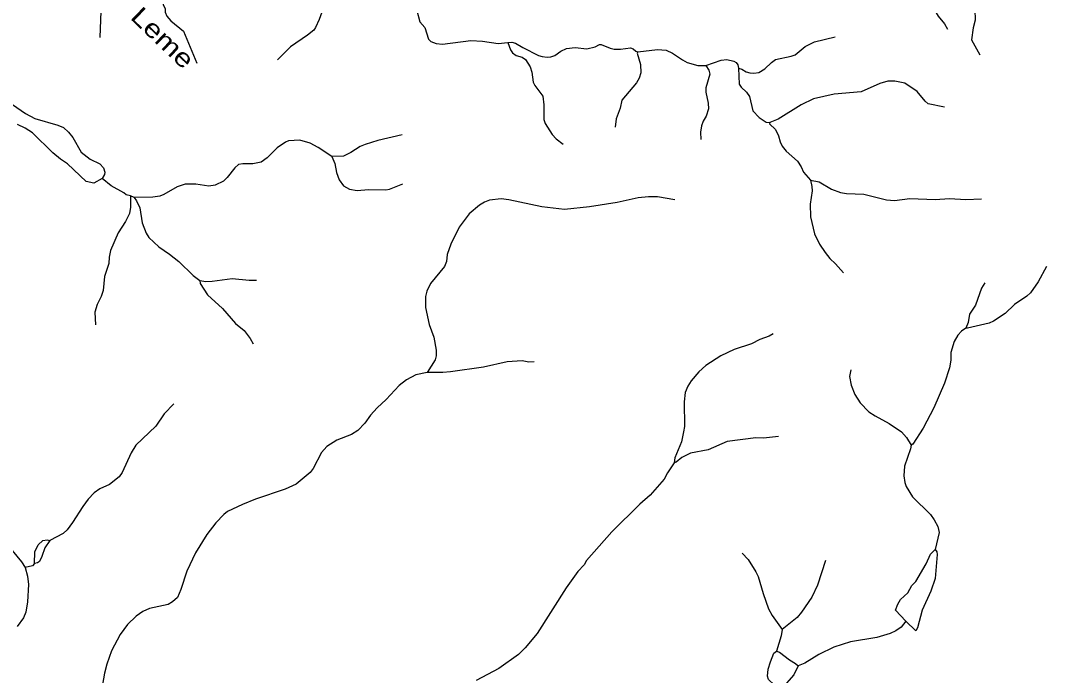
# Model space of a CAD drawing. Extents: x 320.3 to 346.3, y 7455.4 to 7483.3.
# Drawn here: x 336.33 to 340.889, y 7468.339 to 7471.246 of the extents above; entities that cross this region are included whole.
import ezdxf
from ezdxf.enums import TextEntityAlignment as Align

# ---------------------------------------------------------------- set-up
doc = ezdxf.new("R2010")
doc.units = 0
doc.header["$LTSCALE"] = 0.032
doc.layers.add('2', color=7, linetype='Continuous', lineweight=25)
doc.layers.add('7', color=7, linetype='Continuous', lineweight=25)
doc.layers.add('61', color=7, linetype='Continuous')

msp = doc.modelspace()

# ---------------------------------------------------------------- linework, layer by layer
at = {"layer": '2'}
for points in [[(336.2936, 7470.8732), (336.3515, 7470.8329), (336.3936, 7470.8111), (336.495, 7470.7824), (336.5211, 7470.7708), (336.5435, 7470.7511), (336.5628, 7470.7274), (336.5991, 7470.6626), (336.6389, 7470.6306), (336.682, 7470.6101), (336.6983, 7470.5923), (336.7044, 7470.5734), (336.7024, 7470.5629), (336.6931, 7470.5457), (336.6551, 7470.525), (336.6209, 7470.5323), (336.5385, 7470.6101), (336.5073, 7470.6312), (336.4734, 7470.6595), (336.3826, 7470.7483), (336.3499, 7470.7691), (336.3167, 7470.7855)], [(336.2435, 7468.9524), (336.334, 7468.8432), (336.3502, 7468.8174), (336.3614, 7468.7803), (336.3657, 7468.7427), (336.3613, 7468.6653), (336.353, 7468.6196), (336.3435, 7468.5944), (336.3141, 7468.5555)]]:
    msp.add_lwpolyline(points, dxfattribs=at)
for points in [[(336.3924, 7468.8355), (336.3939, 7468.8883), (336.408, 7468.9181), (336.4286, 7468.9375), (336.448, 7468.9407), (336.4593, 7468.9373), (336.4376, 7468.9053), (336.4245, 7468.8662), (336.4139, 7468.845), (336.405, 7468.8385)], [(340.2172, 7468.6285), (340.2278, 7468.655), (340.2404, 7468.6762), (340.2723, 7468.7057), (340.2904, 7468.7381), (340.3077, 7468.7554), (340.3544, 7468.8343), (340.3739, 7468.877), (340.3939, 7468.8982), (340.4012, 7468.8874), (340.4028, 7468.8754), (340.394, 7468.7697), (340.3751, 7468.7135), (340.3368, 7468.6293), (340.3156, 7468.5495), (340.3078, 7468.5362), (340.2642, 7468.5802)], [(339.6484, 7468.3352), (339.6519, 7468.3668), (339.6621, 7468.3988), (339.6775, 7468.4374), (339.689, 7468.4466), (339.7019, 7468.4428), (339.7462, 7468.408), (339.7741, 7468.3923), (339.785, 7468.381), (339.7659, 7468.3418), (339.7113, 7468.28), (339.7034, 7468.2741), (339.6791, 7468.2965), (339.653, 7468.3207)]]:
    msp.add_lwpolyline(points, close=True, dxfattribs=at)
at = {"layer": '7'}
msp.add_line((336.8346, 7470.4601), (336.818, 7470.4679), dxfattribs=at)
for points in [[(337.8245, 7471.6577), (337.8019, 7471.6177), (337.7682, 7471.5712), (337.7578, 7471.5468), (337.7362, 7471.4713), (337.7184, 7471.4348), (337.6965, 7471.4031), (337.6821, 7471.3734), (337.6709, 7471.3345), (337.6679, 7471.2832), (337.6572, 7471.2506), (337.6412, 7471.2156), (337.6326, 7471.2039), (337.6054, 7471.1817), (337.5299, 7471.1296), (337.4719, 7471.0718)], [(340.5465, 7471.6575), (340.5307, 7471.6427), (340.5107, 7471.6328), (340.4993, 7471.6329), (340.4717, 7471.6431), (340.463, 7471.6431), (340.4505, 7471.6351), (340.437, 7471.617), (340.3878, 7471.5971), (340.374, 7471.5652), (340.3702, 7471.528), (340.3492, 7471.4691), (340.3399, 7471.4106), (340.341, 7471.3886), (340.3486, 7471.3651), (340.4079, 7471.2651), (340.4358, 7471.2317), (340.4495, 7471.2085)], [(336.6313, 7471.5267), (336.6561, 7471.5244), (336.6661, 7471.52), (336.6994, 7471.4935), (336.7308, 7471.4557), (336.7439, 7471.4481), (336.7738, 7471.4366), (336.8591, 7471.4186), (336.8819, 7471.4086), (336.8942, 7471.3985), (336.9149, 7471.3903), (336.9351, 7471.3743), (336.9577, 7471.3423), (336.9644, 7471.3133), (336.9719, 7471.3004), (336.9723, 7471.2834), (336.9801, 7471.2654), (336.9981, 7471.2449), (337.0541, 7471.1998), (337.1139, 7471.0573)], [(336.6313, 7471.5267), (336.6701, 7471.4709), (336.6945, 7471.4072), (336.6984, 7471.3518), (336.6872, 7471.288), (336.6827, 7471.1715)], [(340.6429, 7471.4321), (340.6321, 7471.3986), (340.5829, 7471.3306), (340.5708, 7471.2959), (340.5716, 7471.2481), (340.5624, 7471.2141), (340.556, 7471.1605), (340.5919, 7471.0943)], [(338.0912, 7471.2904), (338.1045, 7471.24), (338.1259, 7471.2152), (338.1421, 7471.164), (338.1528, 7471.1538), (338.1771, 7471.1445), (338.2053, 7471.1416), (338.3308, 7471.1575), (338.3822, 7471.1548), (338.4515, 7471.1441), (338.4949, 7471.1485)], [(339.5196, 7471.0354), (339.5345, 7471.0305), (339.5541, 7471.0189), (339.5705, 7471.0144), (339.5886, 7471.013), (339.6112, 7471.0162), (339.6368, 7471.0317), (339.6668, 7471.0606), (339.6849, 7471.0734), (339.7548, 7471.0874), (339.7719, 7471.0936), (339.8164, 7471.1314), (339.8573, 7471.1522), (339.9498, 7471.174)], [(338.4949, 7471.1485), (338.5132, 7471.1502), (338.5288, 7471.1458), (338.5621, 7471.1261), (338.6307, 7471.0914), (338.6482, 7471.0866), (338.6703, 7471.0841), (338.6864, 7471.0852), (338.7047, 7471.0911), (338.7311, 7471.11), (338.7556, 7471.1218), (338.7942, 7471.127), (338.8467, 7471.1212), (338.8836, 7471.1302), (338.9023, 7471.1406), (338.9102, 7471.1401), (338.9497, 7471.123), (338.968, 7471.1188), (338.9956, 7471.1199), (339.0398, 7471.1258), (339.0525, 7471.1214), (339.0633, 7471.1105), (339.0732, 7471.1079)], [(338.4949, 7471.1485), (338.5069, 7471.1158), (338.5166, 7471.1024), (338.5321, 7471.0918), (338.5593, 7471.0839), (338.5743, 7471.0736), (338.5938, 7471.0409), (338.6012, 7471.0178), (338.6081, 7470.9723), (338.6156, 7470.9575), (338.6505, 7470.91), (338.6553, 7470.8724), (338.6554, 7470.8069), (338.6607, 7470.7899), (338.6916, 7470.7402), (338.7094, 7470.7211), (338.7414, 7470.6977)], [(339.0732, 7471.1079), (339.0705, 7471.1008), (339.0847, 7471.0516), (339.0866, 7471.0137), (339.0784, 7470.99), (339.0672, 7470.9704), (339.0019, 7470.8931), (338.9939, 7470.8574), (338.9758, 7470.8099), (338.9723, 7470.7733)], [(339.0732, 7471.1079), (339.1596, 7471.1175), (339.1993, 7471.115), (339.227, 7471.1011), (339.2709, 7471.0713), (339.2924, 7471.0603), (339.3391, 7471.0469), (339.3757, 7471.0467)], [(339.3757, 7471.0467), (339.4432, 7471.0701), (339.4684, 7471.0727), (339.4992, 7471.0655), (339.5098, 7471.0597), (339.5167, 7471.0496), (339.5196, 7471.0354)], [(339.3757, 7471.0467), (339.388, 7471.0262), (339.3922, 7471.0088), (339.3746, 7470.947), (339.3753, 7470.9276), (339.3854, 7470.8798), (339.3863, 7470.8547), (339.3767, 7470.8219), (339.3634, 7470.7993), (339.3561, 7470.7789), (339.3507, 7470.7507), (339.3521, 7470.7178)], [(339.5196, 7471.0354), (339.5225, 7470.9642), (339.5317, 7470.95), (339.5557, 7470.9287), (339.5691, 7470.9098), (339.5842, 7470.8452), (339.612, 7470.8158), (339.6437, 7470.7957), (339.6587, 7470.7937)], [(340.4358, 7470.861), (340.3624, 7470.877), (340.3491, 7470.8886), (340.3141, 7470.931), (340.2595, 7470.9677), (340.2144, 7470.9767), (340.1844, 7470.977), (340.1478, 7470.9672), (340.0648, 7470.9305), (339.945, 7470.9189), (339.8528, 7470.8986), (339.7986, 7470.8721), (339.6966, 7470.8082), (339.6587, 7470.7937)], [(339.6587, 7470.7937), (339.6585, 7470.7883), (339.6842, 7470.7622), (339.6974, 7470.7348), (339.7046, 7470.7072), (339.7139, 7470.6881), (339.7324, 7470.6659), (339.7823, 7470.6213), (339.799, 7470.5975), (339.8085, 7470.5727), (339.8398, 7470.5382)], [(337.7138, 7470.6424), (337.6522, 7470.6832), (337.6164, 7470.7018), (337.5709, 7470.715), (337.5201, 7470.7118), (337.5077, 7470.707), (337.4707, 7470.6813), (337.4258, 7470.6367), (337.3991, 7470.6181), (337.3627, 7470.6099), (337.3172, 7470.6107), (337.2986, 7470.6075), (337.282, 7470.5924), (337.2473, 7470.5488), (337.2311, 7470.5331), (337.1947, 7470.5151), (337.1664, 7470.5112), (337.108, 7470.5192), (337.0617, 7470.52), (337.0262, 7470.5074), (336.9672, 7470.4736), (336.9481, 7470.4673), (336.9173, 7470.4617), (336.8346, 7470.4601)], [(338.0254, 7470.7395), (337.9168, 7470.7144), (337.8605, 7470.6967), (337.8387, 7470.6873), (337.7978, 7470.6604), (337.7653, 7470.6437), (337.7138, 7470.6424)], [(337.7138, 7470.6424), (337.7269, 7470.6112), (337.7344, 7470.5712), (337.7452, 7470.539), (337.7644, 7470.5124), (337.7912, 7470.4981), (337.8257, 7470.4917), (337.8754, 7470.4964), (337.9525, 7470.4942), (337.9696, 7470.4975), (338.0286, 7470.5207)], [(336.818, 7470.4679), (336.7995, 7470.4718), (336.7884, 7470.4821), (336.7328, 7470.5129), (336.6931, 7470.5457)], [(339.8398, 7470.5382), (339.8463, 7470.5099), (339.8469, 7470.49), (339.838, 7470.4308), (339.8396, 7470.3754), (339.8578, 7470.3001), (339.8798, 7470.2536), (339.905, 7470.2167), (339.9259, 7470.19), (339.9514, 7470.1664), (339.9869, 7470.1257)], [(339.8398, 7470.5382), (339.8793, 7470.5308), (339.934, 7470.4979), (339.9737, 7470.4836), (340.0005, 7470.4789), (340.0766, 7470.4755), (340.1784, 7470.4503), (340.214, 7470.4481), (340.2822, 7470.456), (340.3942, 7470.4512), (340.4574, 7470.4558), (340.5303, 7470.4512), (340.5999, 7470.4547)], [(336.818, 7470.4679), (336.8191, 7470.4179), (336.8141, 7470.3903), (336.7968, 7470.3545), (336.7638, 7470.3032), (336.7296, 7470.2249), (336.7235, 7470.1959), (336.7217, 7470.1672), (336.7033, 7470.1105), (336.6966, 7470.0484), (336.6877, 7470.0212), (336.6708, 7469.9861), (336.6604, 7469.9521), (336.6634, 7469.8956)], [(336.8346, 7470.4601), (336.8451, 7470.4459), (336.8599, 7470.415), (336.8701, 7470.3488), (336.8884, 7470.3021), (336.9006, 7470.2837), (336.9445, 7470.2424), (336.9922, 7470.2094), (337.0325, 7470.1759), (337.097, 7470.1138), (337.1271, 7470.0916)], [(339.237, 7470.4499), (339.1595, 7470.4632), (339.1203, 7470.4639), (339.0737, 7470.4588), (338.9813, 7470.4379), (338.8581, 7470.4188), (338.7468, 7470.4081), (338.6456, 7470.4197), (338.5003, 7470.4509), (338.465, 7470.4549), (338.4142, 7470.4483), (338.3914, 7470.4399), (338.3686, 7470.427), (338.3238, 7470.3887), (338.2794, 7470.3293), (338.2413, 7470.2537), (338.2263, 7470.2073), (338.2219, 7470.177), (338.2143, 7470.1537), (338.1519, 7470.0784), (338.1351, 7470.0453), (338.1292, 7470.0206), (338.1297, 7469.972), (338.1457, 7469.8965), (338.1661, 7469.84), (338.1774, 7469.7828), (338.1772, 7469.7578), (338.1727, 7469.7397), (338.1367, 7469.6844)], [(340.8887, 7470.1546), (340.8515, 7470.0865), (340.8178, 7470.0378), (340.8016, 7470.023), (340.7464, 7469.9863), (340.7045, 7469.9454), (340.6532, 7469.912), (340.6334, 7469.903), (340.5373, 7469.8803), (340.53, 7469.8809)], [(337.1271, 7470.0916), (337.1538, 7470.0881), (337.1808, 7470.0893), (337.2709, 7470.1014), (337.3452, 7470.0931), (337.3786, 7470.0943)], [(337.1271, 7470.0916), (337.1279, 7470.0788), (337.1599, 7470.0289), (337.2279, 7469.9673), (337.2846, 7469.9017), (337.3231, 7469.8705), (337.3503, 7469.8342), (337.3641, 7469.8103)], [(340.6153, 7470.082), (340.6003, 7470.0585), (340.5729, 7469.9832), (340.5462, 7469.9431), (340.5407, 7469.9056), (340.53, 7469.8809)], [(340.53, 7469.8809), (340.511, 7469.8677), (340.4945, 7469.8495), (340.4788, 7469.8209), (340.4634, 7469.7722), (340.4631, 7469.7378), (340.458, 7469.7052), (340.4362, 7469.6371), (340.3886, 7469.5274), (340.3403, 7469.4364), (340.2948, 7469.3663), (340.2875, 7469.3614)], [(339.6747, 7469.8561), (339.6566, 7469.8453), (339.6151, 7469.8305), (339.5773, 7469.8113), (339.5011, 7469.7858), (339.4416, 7469.7578), (339.3749, 7469.7141), (339.3434, 7469.6863), (339.3093, 7469.6472), (339.2947, 7469.6233), (339.2834, 7469.5955), (339.2781, 7469.5542), (339.2796, 7469.4444), (339.2762, 7469.4201), (339.2666, 7469.3763), (339.2372, 7469.3044), (339.2348, 7469.2823)], [(338.6127, 7469.7306), (338.5878, 7469.7301), (338.5587, 7469.7349), (338.4922, 7469.7317), (338.3871, 7469.7081), (338.2404, 7469.6871), (338.207, 7469.6832), (338.1367, 7469.6844)], [(340.019, 7469.696), (340.0135, 7469.6659), (340.0214, 7469.627), (340.0378, 7469.5868), (340.0615, 7469.549), (340.0996, 7469.5096), (340.1273, 7469.4912), (340.1897, 7469.4576), (340.2441, 7469.4199), (340.2674, 7469.3959), (340.2875, 7469.3614)], [(338.1367, 7469.6844), (338.0857, 7469.6735), (338.0452, 7469.6517), (338.0129, 7469.6264), (337.9546, 7469.5633), (337.9139, 7469.5274), (337.8852, 7469.4943), (337.8597, 7469.4583), (337.8286, 7469.4268), (337.8009, 7469.4082), (337.7353, 7469.3838), (337.6908, 7469.3547), (337.6671, 7469.329), (337.6295, 7469.2577), (337.6161, 7469.2393), (337.5541, 7469.1881), (337.5064, 7469.1655), (337.3745, 7469.1215), (337.3168, 7469.098), (337.249, 7469.0663), (337.2326, 7469.0528), (337.1978, 7469.0161), (337.1577, 7468.9645), (337.1073, 7468.8838), (337.0682, 7468.8022), (337.0427, 7468.7197), (337.0267, 7468.6852), (337.0052, 7468.6656), (336.9851, 7468.6544), (336.9035, 7468.6354), (336.8727, 7468.622), (336.8439, 7468.6026), (336.8052, 7468.5653), (336.7729, 7468.5206), (336.7344, 7468.4484), (336.7134, 7468.3887), (336.7025, 7468.3484), (336.6946, 7468.2985)], [(337.0117, 7469.5448), (336.9681, 7469.4997), (336.9314, 7469.4454), (336.8427, 7469.3614), (336.8213, 7469.3273), (336.782, 7469.2397), (336.7679, 7469.2207), (336.725, 7469.187), (336.6827, 7469.167), (336.6566, 7469.149), (336.6305, 7469.1216), (336.6059, 7469.0895), (336.5614, 7469.0174), (336.5376, 7468.9855), (336.5197, 7468.9684), (336.4593, 7468.9373)], [(339.6972, 7469.3992), (339.6306, 7469.3919), (339.5973, 7469.3939), (339.4702, 7469.377), (339.385, 7469.341), (339.307, 7469.3257), (339.2685, 7469.3063), (339.2432, 7469.2852), (339.2348, 7469.2823)], [(340.2875, 7469.3614), (340.285, 7469.3449), (340.2577, 7469.2672), (340.2549, 7469.2245), (340.2589, 7469.1959), (340.2655, 7469.1775), (340.2926, 7469.1324), (340.3729, 7469.0527), (340.3896, 7469.0302), (340.4056, 7469.0003), (340.4111, 7468.9738), (340.3939, 7468.8982)], [(339.2348, 7469.2823), (339.2044, 7469.2385), (339.1902, 7469.2098), (339.1278, 7469.1389), (339.0813, 7469.0991), (338.9577, 7468.9764), (338.8442, 7468.849), (338.8338, 7468.8294), (338.8066, 7468.8), (338.7539, 7468.7271), (338.6248, 7468.5248), (338.572, 7468.4609), (338.5425, 7468.4323), (338.4549, 7468.3695), (338.3544, 7468.3169)], [(339.5371, 7468.8819), (339.5626, 7468.8535), (339.5971, 7468.7995), (339.6075, 7468.7784), (339.6291, 7468.703), (339.6535, 7468.634), (339.6695, 7468.6043), (339.7138, 7468.5428)], [(336.3924, 7468.8355), (336.3827, 7468.826), (336.3502, 7468.8174)], [(339.9064, 7468.8497), (339.8705, 7468.7391), (339.8459, 7468.686), (339.8001, 7468.6196), (339.7802, 7468.5966), (339.7138, 7468.5428)], [(340.2642, 7468.5802), (340.2429, 7468.5533), (340.2195, 7468.5368), (340.1935, 7468.5249), (340.1346, 7468.5069), (340.0171, 7468.4876), (339.9439, 7468.4643), (339.8771, 7468.4316), (339.8146, 7468.3932), (339.785, 7468.381)], [(339.7138, 7468.5428), (339.7103, 7468.515), (339.689, 7468.4466)]]:
    msp.add_lwpolyline(points, dxfattribs=at)

# ---------------------------------------------------------------- texts
at = {"layer": '61', "width": 1.25}
msp.add_text('Leme', height=0.08, rotation=316.225, dxfattribs=at).set_placement((336.9342, 7471.1411), align=Align.CENTER)

doc.saveas('drawing.dxf')
